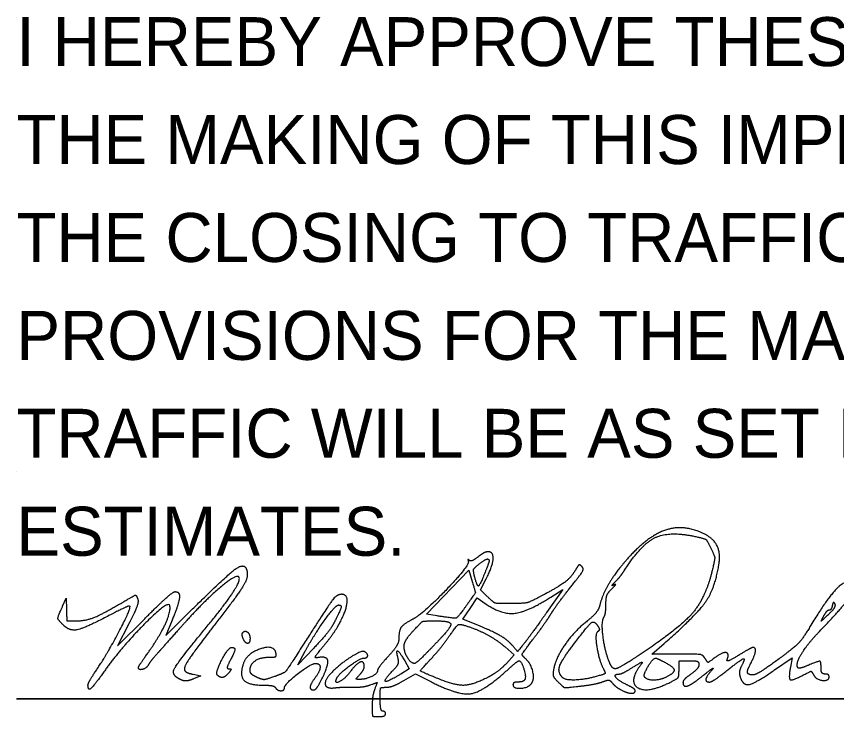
# Model space of a CAD drawing. Extents: x 0 to 34, y 0 to 22.
# Drawn here: x 24.528 to 26.875, y 8.875 to 10.877 of the extents above; entities that cross this region are included whole.
import ezdxf

# ---------------------------------------------------------------- set-up
doc = ezdxf.new("R2010")
doc.units = 0
for name, color, linetype in [('Default', 7, 'Continuous'), ('SH_Data', 7, 'Continuous'), ('SH_Text', 7, 'Continuous')]:
    doc.layers.add(name, color=color, linetype=linetype)

msp = doc.modelspace()

# ---------------------------------------------------------------- linework, layer by layer
at = {"layer": 'SH_Data'}
for p, q in [((24.5279, 10.875), (24.5279, 10.875)), ((24.5279, 9.5762), (24.5279, 9.5762)), ((24.5279, 9.5762), (24.5279, 9.5762)), ((24.5279, 8.9262), (28.0279, 8.9262)), ((24.5289, 8.9265), (28.0289, 8.9265))]:
    msp.add_line(p, q, dxfattribs=at)
at = {"layer": 'SH_Text'}
for p, q in [((26.87, 9.1975), (26.87, 9.1975)), ((25.1761, 9.0995), (25.1761, 9.0995)), ((25.1029, 8.9937), (25.1029, 8.9937)), ((24.7327, 8.9654), (24.7327, 8.9654))]:
    msp.add_line(p, q, dxfattribs=at)
for points in [[(25.7321, 9.1629), (25.7017, 9.1677), (25.8226, 9.2934), (25.8321, 9.2613)], [(25.876, 9.2178), (25.8562, 9.2377), (25.872, 9.2688)], [(26.0565, 9.2162), (26.0916, 9.2385), (26.0449, 9.1724)], [(24.6602, 9.1904), (24.6707, 9.2132), (24.6713, 9.1809)], [(25.8455, 9.1371), (25.8052, 9.1535), (25.8257, 9.1839), (25.8461, 9.2142), (25.8719, 9.1966)], [(24.9732, 9.1503), (24.9552, 9.1068), (25.0321, 9.1828)], [(24.8486, 9.1383), (24.8174, 9.0777), (24.8949, 9.1549)], [(26.4183, 9.0536), (26.3462, 9.0536), (26.3809, 9.084)], [(25.3787, 9.0708), (25.3333, 9.0232), (25.3541, 9.0618)], [(25.9259, 9.0741), (25.9525, 9.0511), (25.9297, 9.027)], [(26.6972, 9.0082), (26.7475, 9.0426), (26.7426, 9.0167)], [(25.6388, 9.0343), (25.6519, 9.0113), (25.6274, 8.9964)], [(25.0336, 8.9959), (25.0557, 8.9914), (25.0349, 8.9828)], [(25.6362, 8.9778), (25.6695, 8.9968), (25.7153, 8.9739)]]:
    msp.add_lwpolyline(points, dxfattribs=at)
for points in [[(26.4959, 9.3973), (26.4391, 9.4257), (26.3338, 9.3915), (26.2761, 9.326)], [(26.2679, 9.2936), (26.315, 9.3672), (26.3955, 9.406), (26.4689, 9.3903)], [(26.4689, 9.3903), (26.4965, 9.3844), (26.5044, 9.3786), (26.5149, 9.3565)], [(26.5376, 9.3082), (26.5431, 9.341), (26.523, 9.3837), (26.4959, 9.3973)], [(25.8775, 9.3462), (25.8718, 9.3462), (25.8586, 9.3394), (25.8482, 9.3312)], [(25.872, 9.2688), (25.8903, 9.3047), (25.8933, 9.3462), (25.8775, 9.3462)], [(26.5149, 9.3565), (26.5257, 9.3338), (26.5262, 9.3243), (26.5186, 9.2924)], [(25.8208, 9.3189), (25.8244, 9.3072), (25.6913, 9.1683), (25.662, 9.1533)], [(25.8237, 9.3217), (25.8207, 9.3247), (25.8194, 9.3235), (25.8208, 9.3189)], [(25.8482, 9.3312), (25.8377, 9.323), (25.8267, 9.3187), (25.8237, 9.3217)], [(25.8502, 9.3099), (25.8661, 9.3228), (25.8803, 9.3274), (25.8803, 9.3197)], [(25.8803, 9.3197), (25.8803, 9.3177), (25.8748, 9.3023), (25.8681, 9.2855)], [(26.2761, 9.326), (26.2425, 9.2878), (26.2045, 9.224), (26.1969, 9.1929)], [(25.0321, 9.1828), (25.1265, 9.276), (25.179, 9.315), (25.1859, 9.2969)], [(25.1859, 9.2969), (25.1928, 9.2789), (25.1708, 9.2356), (25.124, 9.1752)], [(25.8388, 9.2757), (25.8347, 9.2918), (25.8373, 9.2995), (25.8502, 9.3099)], [(26.1302, 9.2986), (26.1171, 9.2754), (26.0839, 9.2486), (26.0364, 9.2231)], [(26.115, 9.247), (26.1429, 9.2817), (26.1518, 9.2981), (26.146, 9.3039)], [(26.146, 9.3039), (26.1402, 9.3096), (26.1356, 9.3081), (26.1302, 9.2986)], [(26.2413, 9.2604), (26.2497, 9.2688), (26.2617, 9.2838), (26.2679, 9.2936)], [(26.3809, 9.084), (26.4732, 9.1646), (26.5266, 9.241), (26.5376, 9.3082)], [(25.1639, 9.2747), (25.1562, 9.2824), (25.0652, 9.2054), (25.0127, 9.1467)], [(25.0708, 9.1296), (25.125, 9.195), (25.1714, 9.2673), (25.1639, 9.2747)], [(25.8681, 9.2855), (25.8538, 9.2497), (25.8459, 9.2471), (25.8388, 9.2757)], [(26.5186, 9.2924), (26.4997, 9.2138), (26.4232, 9.1258), (26.3068, 9.0488)], [(25.8321, 9.2613), (25.8413, 9.2303), (25.8407, 9.2279), (25.8168, 9.1946)], [(26.0567, 9.1677), (26.0672, 9.1844), (26.0935, 9.2201), (26.115, 9.247)], [(26.2318, 9.2406), (26.2412, 9.2497), (26.2438, 9.2545), (26.2375, 9.2512)], [(26.2375, 9.2512), (26.2313, 9.2478), (26.233, 9.252), (26.2413, 9.2604)], [(26.9139, 9.2335), (26.9139, 9.2748), (26.8522, 9.2218), (26.8013, 9.1366)], [(24.8329, 9.2026), (24.8658, 9.222), (24.8706, 9.223), (24.8749, 9.2117)], [(24.8949, 9.1549), (24.9375, 9.1974), (24.9766, 9.2322), (24.9818, 9.2322)], [(24.9818, 9.2322), (24.9964, 9.2322), (24.9928, 9.198), (24.9732, 9.1503)], [(25.4589, 9.2246), (25.4449, 9.2246), (25.4191, 9.191), (25.3514, 9.0849)], [(25.454, 9.1447), (25.4727, 9.1803), (25.4755, 9.2246), (25.4589, 9.2246)], [(26.0364, 9.2231), (25.999, 9.2031), (25.9818, 9.1984), (25.9432, 9.1982)], [(26.2146, 9.1958), (26.2147, 9.2149), (26.2202, 9.2293), (26.2318, 9.2406)], [(26.8218, 9.1144), (26.8811, 9.1764), (26.9139, 9.2188), (26.9139, 9.2335)], [(24.6976, 9.1486), (24.7254, 9.1486), (24.7745, 9.1681), (24.8329, 9.2026)], [(24.8749, 9.2117), (24.8779, 9.204), (24.8675, 9.1751), (24.8486, 9.1383)], [(25.8719, 9.1966), (25.9162, 9.1664), (25.9904, 9.1743), (26.0565, 9.2162)], [(25.9432, 9.1982), (25.9022, 9.198), (25.8933, 9.2006), (25.876, 9.2178)], [(26.87, 9.1975), (26.8669, 9.2023), (26.8638, 9.2002), (26.8622, 9.1923)], [(24.6618, 9.1369), (24.6467, 9.1521), (24.6464, 9.1602), (24.6602, 9.1904)], [(24.6713, 9.1809), (24.6719, 9.1494), (24.6726, 9.1486), (24.6976, 9.1486)], [(24.7601, 9.0129), (24.7899, 9.0571), (24.857, 9.1864), (24.8525, 9.1909)], [(24.9669, 9.1921), (24.9637, 9.2089), (24.83, 9.0755), (24.7805, 9.0061)], [(24.8525, 9.1909), (24.8509, 9.1925), (24.824, 9.1803), (24.7927, 9.1639)], [(24.9036, 9.0562), (24.9365, 9.102), (24.9703, 9.1746), (24.9669, 9.1921)], [(25.3541, 9.0618), (25.3786, 9.1072), (25.4408, 9.194), (25.449, 9.1941)], [(25.449, 9.1941), (25.4585, 9.1942), (25.4555, 9.1799), (25.4394, 9.1483)], [(25.8168, 9.1946), (25.7908, 9.1583), (25.7819, 9.155), (25.7321, 9.1629)], [(26.1969, 9.1929), (26.1942, 9.1818), (26.1781, 9.1617), (26.1612, 9.1483)], [(26.2083, 9.1578), (26.2117, 9.1632), (26.2145, 9.1803), (26.2146, 9.1958)], [(26.8528, 9.179), (26.8491, 9.179), (26.842, 9.1713), (26.837, 9.162)], [(26.8514, 9.1672), (26.8644, 9.1795), (26.8727, 9.1931), (26.87, 9.1975)], [(26.8622, 9.1923), (26.8608, 9.185), (26.8566, 9.179), (26.8528, 9.179)], [(24.7927, 9.1639), (24.7234, 9.1276), (24.6801, 9.1187), (24.6618, 9.1369)], [(25.124, 9.1752), (25.0463, 9.0748), (25.006, 9.0165), (25.0087, 9.0084)], [(25.662, 9.1533), (25.6353, 9.1397), (25.6219, 9.1204), (25.6219, 9.0957)], [(26.0449, 9.1724), (26.0192, 9.1361), (25.9908, 9.0971), (25.9818, 9.0857)], [(26.0047, 9.0943), (26.0228, 9.1179), (26.0462, 9.1509), (26.0567, 9.1677)], [(26.2236, 9.0327), (26.2113, 9.0642), (26.2012, 9.1466), (26.2083, 9.1578)], [(26.837, 9.162), (26.8294, 9.1478), (26.8319, 9.1487), (26.8514, 9.1672)], [(25.0127, 9.1467), (24.982, 9.1124), (24.9467, 9.0728), (24.9341, 9.0587)], [(25.0032, 8.9784), (24.9705, 8.9909), (24.9875, 9.029), (25.0708, 9.1296)], [(25.4394, 9.1483), (25.431, 9.1318), (25.4037, 9.0969), (25.3787, 9.0708)], [(25.4074, 9.0777), (25.4242, 9.0979), (25.4452, 9.128), (25.454, 9.1447)], [(25.6634, 9.1201), (25.6869, 9.1457), (25.6934, 9.1486), (25.7275, 9.1486)], [(25.7702, 9.1408), (25.7729, 9.1365), (25.752, 9.1092), (25.7238, 9.08)], [(25.7275, 9.1486), (25.7484, 9.1486), (25.7676, 9.1451), (25.7702, 9.1408)], [(25.7665, 9.105), (25.7867, 9.1338), (25.795, 9.1402), (25.8076, 9.1365)], [(25.8076, 9.1365), (25.8433, 9.126), (25.901, 9.0956), (25.9259, 9.0741)], [(25.9488, 9.0763), (25.9351, 9.0927), (25.8916, 9.1184), (25.8455, 9.1371)], [(26.1612, 9.1483), (26.125, 9.1197), (26.0719, 9.0444), (26.0656, 9.0128)], [(26.1216, 9.081), (26.1643, 9.137), (26.1815, 9.1499), (26.1917, 9.1336)], [(26.1917, 9.1336), (26.1961, 9.1265), (26.1958, 9.1206), (26.1908, 9.1175)], [(26.8013, 9.1366), (26.7788, 9.0991), (26.757, 9.0755), (26.7166, 9.0451)], [(25.1761, 9.0995), (25.1737, 9.1059), (25.1736, 9.1131), (25.1759, 9.1155)], [(25.1759, 9.1155), (25.1825, 9.1221), (25.1963, 9.1108), (25.1963, 9.0987)], [(25.6372, 9.0762), (25.6372, 9.0846), (25.649, 9.1044), (25.6634, 9.1201)], [(26.1908, 9.1175), (26.1824, 9.1123), (26.1948, 9.0354), (26.208, 9.0102)], [(26.7645, 9.0143), (26.756, 9.0228), (26.7887, 9.0798), (26.8218, 9.1144)], [(25.1963, 9.0987), (25.1963, 9.0841), (25.1818, 9.0847), (25.1761, 9.0995)], [(25.3514, 9.0849), (25.3038, 9.0103), (25.2938, 8.9991), (25.2664, 8.9894)], [(25.6219, 9.0957), (25.6219, 9.087), (25.6082, 9.065), (25.5915, 9.0468)], [(25.7142, 9.0403), (25.729, 9.0559), (25.7526, 9.0851), (25.7665, 9.105)], [(25.9818, 9.0857), (25.9629, 9.0617), (25.9613, 9.0612), (25.9488, 9.0763)], [(25.983, 9.0421), (25.9735, 9.05), (25.9767, 9.0577), (26.0047, 9.0943)], [(24.9341, 9.0587), (24.9216, 9.0447), (24.9086, 9.0284), (24.9052, 9.0225)], [(25.1029, 8.9937), (25.0966, 9), (25.1337, 9.0726), (25.1433, 9.0726)], [(25.1433, 9.0726), (25.1539, 9.0726), (25.1525, 9.0601), (25.1391, 9.0342)], [(25.2705, 9.0567), (25.2653, 9.0817), (25.1863, 9.0551), (25.1768, 9.0253)], [(25.3901, 9.0435), (25.3809, 9.0418), (25.3862, 9.0523), (25.4074, 9.0777)], [(25.5242, 9.0605), (25.5169, 9.065), (25.4598, 9.0298), (25.4334, 9.0044)], [(25.522, 9.0422), (25.5322, 9.0422), (25.5337, 9.0546), (25.5242, 9.0605)], [(25.6198, 9.0417), (25.6139, 9.0646), (25.6238, 9.0607), (25.6388, 9.0343)], [(25.6667, 9.027), (25.6568, 9.027), (25.6371, 9.0598), (25.6372, 9.0762)], [(25.7238, 9.08), (25.6957, 9.0508), (25.67, 9.027), (25.6667, 9.027)], [(26.0906, 8.9864), (26.0761, 9.0009), (26.0879, 9.0368), (26.1216, 9.081)], [(26.6355, 9.0726), (26.6328, 9.0726), (26.6141, 9.0624), (26.594, 9.0501)], [(26.6284, 9.0259), (26.6406, 9.0496), (26.6441, 9.0726), (26.6355, 9.0726)], [(24.8771, 9.0156), (24.8771, 9.0176), (24.8891, 9.0359), (24.9036, 9.0562)], [(25.1963, 9.0066), (25.1963, 9.024), (25.2255, 9.0447), (25.2499, 9.0447)], [(25.2499, 9.0447), (25.2669, 9.0447), (25.2723, 9.0479), (25.2705, 9.0567)], [(25.4033, 8.9855), (25.4215, 9.0231), (25.4158, 9.0483), (25.3901, 9.0435)], [(25.4442, 8.9841), (25.449, 8.9959), (25.5111, 9.0422), (25.522, 9.0422)], [(25.5915, 9.0468), (25.5748, 9.0287), (25.5611, 9.0105), (25.5611, 9.0064)], [(25.6025, 9.0037), (25.617, 9.0188), (25.6226, 9.0312), (25.6198, 9.0417)], [(25.7404, 8.981), (25.6852, 9.0032), (25.6833, 9.0076), (25.7142, 9.0403)], [(26.0008, 8.9686), (26.011, 8.9809), (25.9994, 9.0285), (25.983, 9.0421)], [(26.3068, 9.0488), (26.276, 9.0285), (26.2465, 9.0118), (26.2413, 9.0118)], [(26.325, 8.9888), (26.3211, 8.9952), (26.3494, 9.0422), (26.3571, 9.0422)], [(26.3571, 9.0422), (26.3586, 9.0422), (26.37, 9.037), (26.3823, 9.0306)], [(26.4984, 9.0411), (26.492, 9.0512), (26.4771, 9.0536), (26.4183, 9.0536)], [(26.527, 9.0438), (26.508, 9.0298), (26.5056, 9.0296), (26.4984, 9.0411)], [(26.5614, 9.0379), (26.5684, 9.0562), (26.5483, 9.0596), (26.527, 9.0438)], [(26.5576, 9.0042), (26.6003, 9.0379), (26.6148, 9.0428), (26.6022, 9.0191)], [(26.594, 9.0501), (26.5739, 9.0377), (26.5592, 9.0322), (26.5614, 9.0379)], [(26.7166, 9.0451), (26.6656, 9.0068), (26.6297, 8.9895), (26.6204, 8.9987)], [(24.7327, 8.9654), (24.7327, 8.9692), (24.7451, 8.9905), (24.7601, 9.0129)], [(24.9052, 9.0225), (24.8996, 9.0126), (24.8771, 9.007), (24.8771, 9.0156)], [(25.1391, 9.0342), (25.1313, 9.019), (25.1303, 9.0118), (25.1363, 9.0118)], [(25.1363, 9.0118), (25.1425, 9.0118), (25.1423, 9.0085), (25.1355, 9.0004)], [(25.1768, 9.0253), (25.166, 8.9912), (25.1932, 8.9646), (25.2391, 8.9646)], [(25.2951, 8.9579), (25.2951, 8.9677), (25.3709, 9.027), (25.3835, 9.027)], [(25.3835, 9.027), (25.3971, 9.027), (25.3964, 9.0043), (25.3823, 8.9856)], [(25.5231, 9.0181), (25.5231, 9.0347), (25.5008, 9.0271), (25.4844, 9.0048)], [(25.5105, 8.9953), (25.5175, 9.0029), (25.5231, 9.0132), (25.5231, 9.0181)], [(25.9297, 9.027), (25.9172, 9.0137), (25.8939, 8.9961), (25.8779, 8.9879)], [(25.9317, 9.0072), (25.9483, 9.0223), (25.9638, 9.0346), (25.966, 9.0346)], [(25.966, 9.0346), (25.9727, 9.0346), (25.9869, 8.9877), (25.9824, 8.9805)], [(26.0656, 9.0128), (26.0622, 8.996), (26.0653, 8.9864), (26.078, 8.9737)], [(26.2413, 9.0118), (26.236, 9.0118), (26.2281, 9.0212), (26.2236, 9.0327)], [(26.2522, 8.9966), (26.2569, 8.9966), (26.2751, 9.0057), (26.2928, 9.0168)], [(26.2928, 9.0168), (26.3105, 9.028), (26.3212, 9.0322), (26.3166, 9.0263)], [(26.3166, 9.0263), (26.2778, 8.9762), (26.3316, 8.9402), (26.3971, 8.9724)], [(26.3823, 9.0306), (26.4081, 9.0172), (26.4112, 9.0006), (26.39, 8.9892)], [(26.4237, 9.0081), (26.4237, 9.0333), (26.4254, 9.0346), (26.4579, 9.0346)], [(26.4579, 9.0346), (26.4726, 9.0346), (26.4807, 9.0307), (26.4807, 9.0237)], [(26.4807, 9.0237), (26.4807, 9.0177), (26.4705, 9.0055), (26.4579, 8.9966)], [(26.4951, 8.9943), (26.5144, 9.0098), (26.5241, 9.0155), (26.5168, 9.007)], [(26.6022, 9.0191), (26.5976, 9.0106), (26.596, 8.9969), (26.5986, 8.9887)], [(26.6204, 8.9987), (26.6182, 9.001), (26.6218, 9.0132), (26.6284, 9.0259)], [(26.7426, 9.0167), (26.7365, 8.9839), (26.7468, 8.9771), (26.7781, 8.9933)], [(26.7947, 9.0221), (26.7799, 9.0159), (26.7663, 9.0124), (26.7645, 9.0143)], [(26.8303, 9.0105), (26.8303, 9.032), (26.8237, 9.0342), (26.7947, 9.0221)], [(24.7805, 9.0061), (24.7493, 8.9623), (24.7327, 8.9482), (24.7327, 8.9654)], [(25.0087, 9.0084), (25.0102, 9.004), (25.0214, 8.9983), (25.0336, 8.9959)], [(25.1355, 9.0004), (25.1257, 8.9885), (25.1111, 8.9855), (25.1029, 8.9937)], [(25.2159, 8.9873), (25.2051, 8.9922), (25.1963, 9.0009), (25.1963, 9.0066)], [(25.2664, 8.9894), (25.2419, 8.9807), (25.2313, 8.9803), (25.2159, 8.9873)], [(25.4334, 9.0044), (25.4097, 8.9817), (25.4133, 8.9538), (25.4395, 8.9573)], [(25.4844, 9.0048), (25.4682, 8.9829), (25.4371, 8.9669), (25.4442, 8.9841)], [(25.5102, 8.9814), (25.4991, 8.9814), (25.4991, 8.9826), (25.5105, 8.9953)], [(25.5611, 9.0064), (25.5611, 8.9977), (25.5279, 8.9814), (25.5102, 8.9814)], [(25.6274, 8.9964), (25.5902, 8.9737), (25.5774, 8.9775), (25.6025, 9.0037)], [(25.7153, 8.9739), (25.7929, 8.9351), (25.864, 8.9461), (25.9317, 9.0072)], [(25.8779, 8.9879), (25.8347, 8.9656), (25.7848, 8.9631), (25.7404, 8.981)], [(26.1863, 8.9894), (26.1541, 8.9805), (26.0983, 8.9787), (26.0906, 8.9864)], [(26.208, 9.0102), (26.2137, 8.9996), (26.2098, 8.9959), (26.1863, 8.9894)], [(26.2739, 8.9662), (26.2498, 8.9775), (26.2363, 8.9966), (26.2522, 8.9966)], [(26.39, 8.9892), (26.3714, 8.9793), (26.3311, 8.979), (26.325, 8.9888)], [(26.3971, 8.9724), (26.4186, 8.983), (26.4237, 8.9898), (26.4237, 9.0081)], [(26.4579, 8.9966), (26.4454, 8.9876), (26.4351, 8.9771), (26.4351, 8.9733)], [(26.4351, 8.9733), (26.4351, 8.9581), (26.4617, 8.9674), (26.4951, 8.9943)], [(26.5168, 9.007), (26.502, 8.9898), (26.4994, 8.9738), (26.5113, 8.9738)], [(26.5113, 8.9738), (26.5156, 8.9738), (26.5365, 8.9874), (26.5576, 9.0042)], [(26.5986, 8.9887), (26.6067, 8.9633), (26.6418, 8.9702), (26.6972, 9.0082)], [(26.7781, 8.9933), (26.8002, 9.0047), (26.8028, 9.0047), (26.8091, 8.9936)], [(26.8091, 8.9936), (26.8164, 8.9804), (26.8531, 8.9765), (26.8531, 8.989)], [(26.8417, 8.9966), (26.8355, 8.9966), (26.8303, 9.0028), (26.8303, 9.0105)], [(26.8531, 8.989), (26.8531, 8.9931), (26.848, 8.9966), (26.8417, 8.9966)], [(25.0349, 8.9828), (25.0234, 8.9781), (25.0092, 8.9761), (25.0032, 8.9784)], [(25.2391, 8.9646), (25.2532, 8.9646), (25.2667, 8.9616), (25.269, 8.9578)], [(25.3823, 8.9856), (25.3694, 8.9686), (25.3676, 8.951), (25.3788, 8.951)], [(25.3788, 8.951), (25.3831, 8.951), (25.3941, 8.9665), (25.4033, 8.9855)], [(25.4902, 8.9591), (25.5077, 8.9588), (25.5306, 8.9618), (25.5412, 8.9658)], [(25.5412, 8.9658), (25.5596, 8.9728), (25.5602, 8.9722), (25.5532, 8.954)], [(25.5858, 8.9587), (25.5952, 8.9587), (25.6179, 8.9673), (25.6362, 8.9778)], [(25.9635, 8.9738), (25.9554, 8.9738), (25.9487, 8.9703), (25.9487, 8.9662)], [(25.9487, 8.9662), (25.9487, 8.955), (25.9911, 8.9569), (26.0008, 8.9686)], [(25.9824, 8.9805), (25.9801, 8.9768), (25.9716, 8.9738), (25.9635, 8.9738)], [(26.078, 8.9737), (26.0931, 8.9586), (26.0997, 8.9574), (26.1403, 8.9619)], [(26.1403, 8.9619), (26.1653, 8.9648), (26.1944, 8.9704), (26.205, 8.9744)], [(26.205, 8.9744), (26.2193, 8.9798), (26.2264, 8.979), (26.2328, 8.9711)], [(26.2328, 8.9711), (26.2375, 8.9652), (26.2482, 8.9567), (26.2565, 8.9521)], [(26.2982, 8.9491), (26.2981, 8.9522), (26.2871, 8.9599), (26.2739, 8.9662)], [(25.269, 8.9578), (25.2745, 8.9489), (25.2951, 8.9489), (25.2951, 8.9579)], [(25.4395, 8.9573), (25.45, 8.9586), (25.4728, 8.9595), (25.4902, 8.9591)], [(25.5532, 8.954), (25.5492, 8.9434), (25.5459, 8.9213), (25.5459, 8.9049)], [(25.5687, 8.9244), (25.5687, 8.9547), (25.5706, 8.9586), (25.5858, 8.9587)], [(26.2565, 8.9521), (26.2741, 8.9425), (26.2984, 8.9407), (26.2982, 8.9491)], [(25.5763, 8.8902), (25.5721, 8.8902), (25.5687, 8.9056), (25.5687, 8.9244)], [(25.5459, 8.9049), (25.5459, 8.878), (25.5479, 8.875), (25.5649, 8.875)], [(25.5649, 8.875), (25.5754, 8.875), (25.5839, 8.8784), (25.5839, 8.8826)], [(25.5839, 8.8826), (25.5839, 8.8867), (25.5805, 8.8902), (25.5763, 8.8902)]]:
    msp.add_open_spline(points, degree=2, dxfattribs=at)

# ---------------------------------------------------------------- texts
at = {"layer": 'Default'}
for s, p in [('I HEREBY APPROVE THESE PLANS AND DECLARE THAT', (24.5279, 10.735)), ('THE MAKING OF THIS IMPROVEMENT WILL NOT REQUIRE', (24.5279, 10.455)), ('THE CLOSING TO TRAFFIC TO THE HIGHWAY AND THAT', (24.5279, 10.175)), ('PROVISIONS FOR THE MAINTENANCE AND SAFETY OF ', (24.5279, 9.895)), ('TRAFFIC WILL BE AS SET FORTH ON THE PLANS AND', (24.5279, 9.615)), ('ESTIMATES.', (24.5279, 9.335))]:
    msp.add_text(s, height=0.14, dxfattribs=at).set_placement(p)

doc.saveas('drawing.dxf')
